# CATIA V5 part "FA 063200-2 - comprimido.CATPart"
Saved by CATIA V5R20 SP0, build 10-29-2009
Part number: FA 063200-2 - comprimido
Revision: ANY
Definition: UNKNOWN
Nomenclature: FA 063200-2 - comprimido
Source: Unknown
Bounding box of the stored display mesh (mm): x -1.95 to 1.95, y 0 to 5.85, z -1.95 to 1.95
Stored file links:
  C:\Users\Utente\Desktop\IO LAVORO\3D X SITO CF\CUMSA\3D files FA\FA 0632SF\FA 063200-2 - comprimido.CATPart

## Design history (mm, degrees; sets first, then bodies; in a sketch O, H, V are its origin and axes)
Body1 "Cortar-Extruir1" (main body)
  Solid1: solid without history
